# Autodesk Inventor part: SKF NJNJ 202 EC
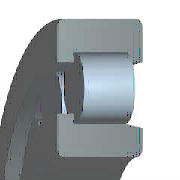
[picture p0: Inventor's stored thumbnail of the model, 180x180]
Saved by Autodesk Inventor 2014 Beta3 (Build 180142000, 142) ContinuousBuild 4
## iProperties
IsCustomPart: 0
Created: 2010-11
Part Number: SKF NJNJ 202 EC
Material: Steel, Mild
Description: Cylindrical Roller Bearings Single Row type NJ SKF
Document SubType Name: Modeling
Standard: SKF NJ
Designer: Beta-8540w
Language: en-US
Size Designation: SKF NJNJ 202 EC
Categories: <MemberInstance><Categories><Category DisplayName="Shaft Parts" InternalName="7f7aeb1f-a693-4053-b835-cee3144e0d98" Mnemonic="SHFT"><Category DisplayName="Beari
Density: 7.86 g/cm^3
Appearance: Steel
Author: Beta-8540w
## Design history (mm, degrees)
node "WorkPlane1"
workplane "Work Plane2"
node "WorkPlane2"
node "Sketch1"
node "WorkPoint1"
node "Sketch3"
node "WorkPoint2"
node "WorkAxis1"
sketch "Sketch4"
  geometry: C1 r 17.5 at (0, 0) reference
hole "Hole1" sketch "Sketch4" diameter "d6" = 15 (= Diam); stored, may be unused: countersink angle "d10" = 60 deg, drill point angle "d12" = 118 deg; dims "d7" = 6, "d8" = 4, "d9" = 2, "d11" = 8
pattern_circular "PolarArray1" dims angle "d31" = 360 deg
fillet "Fillet1" dims "d32" = 0.6 (= r)
body "Solid1"
extrude "Extrusion1" new body distance "d3" = 11 (= B); taper "d4" = 0 deg
revolve "Revolution1" stored, may be unused: angle "d25" = 360 deg
revolve "Revolution2" stored, may be unused: angle "d28" = 360 deg
node "Sketch2" dims "d2" = 35 (= DD)
sketch "Sketch5"
  geometry: L1 (13.95, 1.925)-(15.15, 1.925); L2 (13.95, 0)-(13.95, 1.925); L3 (10.95, 0)-(13.95, 0); L4 (10.95, 1.925)-(10.95, 0); L5 (9.65, 1.925)-(10.95, 1.925); L6 (9.65, 9.075)-(9.65, 1.925); L7 (9.311, 11)-(9.65, 9.075); L8 (13.95, 11)-(9.311, 11); L9 (13.95, 9.075)-(13.95, 11); L10 (15.15, 9.075)-(13.95, 9.075); L11 (15.15, 1.925)-(15.15, 9.075); L12 (-17.5, 0)-(17.5, 0) reference; L13 (-17.5, 11)-(17.5, 11) reference; L14 (0, 34.914)-(0, -22.914); L15 (0, -34.479)-(0, 46.479) reference
  constraints: 24 end point, 5 collinear, 5 horizontal, 5 vertical, 1 point on line
  dimensions: "d16" = 7.15 distance of L1.end L10.start (= msp_l0); "d18" = 1.925 distance of L2.start L1.start (= 0.5 x B - 0.5 x msp_l0); "d24" = 80 deg angle of L7 L8; "d33" = 5.5 distance between parallel lines of L11 L6 (= msp_dd0); "d34" = 27.9 diameter of L9 L14 (= DD1); "d35" = 30.3 diameter of L11 L14 (= EE); "d36" = 21.9 diameter of L4 L14 (= Diam1)
sketch "Sketch6"
  geometry: L1 (12.4, 1.925)-(12.4, 9.075); L2 (15.15, 1.925)-(12.4, 1.925); L3 (15.15, 9.075)-(15.15, 1.925); L4 (12.4, 9.075)-(15.15, 9.075); L5 (-15.15, 9.075)-(15.15, 9.075) reference; L6 (-15.15, 1.925)-(15.15, 1.925) reference; L7 (12.4, 1.925)-(12.4, 9.075); L8 (15.15, 9.075)-(15.15, 1.925) reference
  constraints: 10 end point, 3 collinear, 2 horizontal, 2 vertical
  dimensions: "d27" = 2.75 distance of L1.end L5.end (= 0.5 x msp_dd0)
other parameters: "Diam" = 15 [user parameter; used in 1 equation term], "DD" = 35 [user parameter; used in 1 equation term], "B" = 11 [user parameter; used in 4 equation terms], "r" = 0.6 [user parameter; used in 1 equation term], "Fw" = 19.3 [user parameter; used in 2 equation terms], "Diam1" = 21.9 [user parameter; used in 1 equation term], "EE" = 30.3 [user parameter; used in 3 equation terms], "msp_mdtds" = 24.8 (= 0.5 x Fw + 0.5 x EE) [user parameter; used in 1 equation term], "msp_dd0" = 5.5 (= -0.5 x Fw + 0.5 x EE) [user parameter; used in 3 equation terms], "msp_l0" = 7.15 (= 0.65 x B) [user parameter; used in 2 equation terms], "DD1" = 27.9 [user parameter; used in 1 equation term], "d0" = -11 (computed from B), "d5" = 0, "d13" = 0 (derived), "d15" = 7.8 (derived), "d17" = 2.1 (derived), "d19" = 0 (derived), "d21" = 0 (derived), "d23" = 80 deg (derived), "d26" = 3.25 (derived), "d39" = 0, "d40" = 0, "d41" = 0, "d42" = 0, "d43" = 0
